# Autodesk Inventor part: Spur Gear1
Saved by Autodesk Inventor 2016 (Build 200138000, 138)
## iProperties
Created: 2015-08
Part Number: Spur Gear1
Material: Steel
Document SubType Name: Modeling
Designer: Ugljesa
Categories: <?xml version="1.0" encoding="UTF-16"?> <MemberInstance><Categories><FamilyTemplate><FamilyTemplateParameter ValueType="xs:double" Id="1" ObjectReferenceKey="da
Mass: 1344.39 g
Surface Area: 329.177 cm^2
Volume: 171.26 cm^3
Density: 7.85 g/cm^3
Appearance: Steel
CustomPartVersion: 1
Author: Ugljesa
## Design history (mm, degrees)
sketch "Sketch1"
  geometry: C1 r 56.77 at (0, 0)
  constraints: 1 centre point
  dimensions: "d0" = 113.5407 diameter of C1 (= da_da)
extrude "Extrusion1" new body sketch "Sketch1" distance "d1" = 20 (= da_b); taper "d2" = 0 deg
workplane "Work Plane2"
sketch "Sketch2"
  geometry: C1 r 56.77 at (0, 0) reference; C2 r 54.857 at (0, 0)
  constraints: 1 centre point, 1 coincident
  dimensions: "d3" = 109.71429 diameter of C2 (= da_dw)
feature "Pitch Diameter" sketch "Sketch2" dims "d4" = 10, "d5" = 0
workplane "Work Plane8"
workplane "Work Plane9"
feature "Spur Gear" dims "da_b" = 20, "da_d" = 109.06138, "da_aw" = 80, "da_da" = 113.5407, "da_df" = 103.43638, "da_dw" = 109.71429, angle "da_beta" = 8 deg, "da_lefttooth" = 10, "da_righttooth" = 0
node "Keyway1"
body "Solid1"
body "Srf1"
feature "Hub Keyway"
other parameters: "d17" = 0, "d34" = 0.6545 (computed from da_z), "d39" = 0, "d41" = 0, "d47" = 0, "d48" = 0
